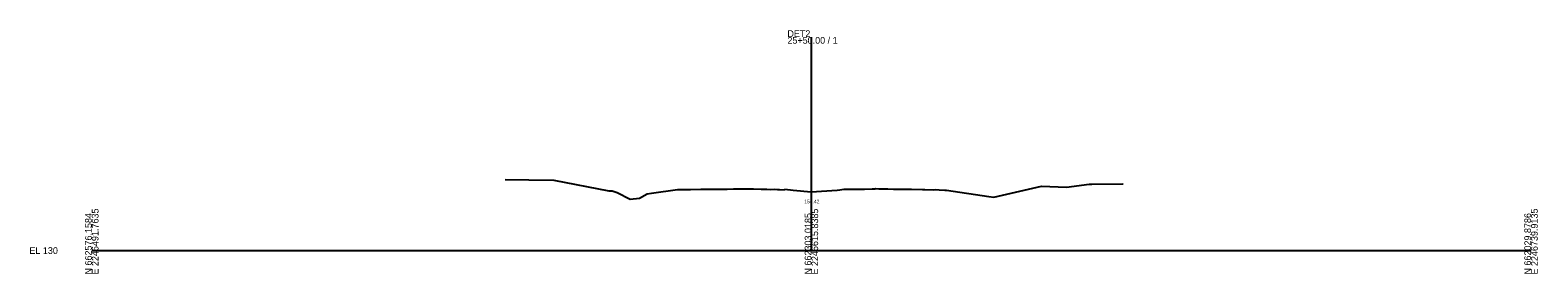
# Model space of a CAD drawing. Extents: x -26 to 603, y -10 to 9526.
# Drawn here: x -26 to 603, y 8490 to 8592 of the extents above; entities that cross this region are included whole.
import ezdxf

# ---------------------------------------------------------------- set-up
doc = ezdxf.new("R2010")
doc.units = 0
for name, color, linetype in [('Default', 7, 'Continuous'), ('Exist Cross Section Cell', 7, 'Continuous'), ('Exist XS Center Line Elevation Label', 7, 'Continuous'), ('Exist XS Ground Line', 7, 'Continuous')]:
    doc.layers.add(name, color=color, linetype=linetype)

msp = doc.modelspace()

# ---------------------------------------------------------------- linework, layer by layer
at = {"layer": 'Exist Cross Section Cell'}
for p, q in [((300, 8500), (300, 8588.93)), ((0, 8500), (300, 8500)), ((300, 8500), (600, 8500))]:
    msp.add_line(p, q, dxfattribs=at)
at = {"layer": 'Exist XS Ground Line'}
for p, q in [((172.27, 8529.64), (182.19, 8529.48)), ((182.19, 8529.48), (192.62, 8529.37)), ((192.62, 8529.37), (215.52, 8524.82)), ((215.52, 8524.82), (216.9, 8524.8)), ((216.9, 8524.8), (219.09, 8524.18)), ((219.09, 8524.18), (224.51, 8521.41)), ((228.36, 8521.82), (231.48, 8523.58)), ((231.48, 8523.58), (233.31, 8523.85)), ((233.31, 8523.85), (244.15, 8525.43)), ((244.15, 8525.43), (246.05, 8525.47)), ((246.05, 8525.47), (246.86, 8525.45)), ((246.86, 8525.45), (247.97, 8525.42)), ((247.97, 8525.42), (248.48, 8525.41)), ((248.48, 8525.41), (249.61, 8525.44)), ((249.61, 8525.44), (253.89, 8525.53)), ((253.89, 8525.53), (257.45, 8525.58)), ((257.45, 8525.58), (259.38, 8525.59)), ((259.38, 8525.59), (260.36, 8525.6)), ((260.36, 8525.6), (260.76, 8525.6)), ((260.76, 8525.6), (261.38, 8525.6)), ((261.38, 8525.6), (261.72, 8525.61)), ((261.72, 8525.61), (263.88, 8525.62)), ((263.88, 8525.62), (264.87, 8525.62)), ((264.87, 8525.62), (267.51, 8525.64)), ((267.51, 8525.64), (270.37, 8525.66)), ((270.37, 8525.66), (271.44, 8525.67)), ((271.44, 8525.67), (273.24, 8525.7)), ((273.24, 8525.7), (273.79, 8525.71)), ((273.79, 8525.71), (275.47, 8525.66)), ((275.47, 8525.66), (275.86, 8525.66)), ((275.86, 8525.66), (278.99, 8525.6)), ((278.99, 8525.6), (281.35, 8525.53)), ((281.35, 8525.53), (282.77, 8525.48)), ((282.77, 8525.48), (284.66, 8525.55)), ((284.66, 8525.55), (285.81, 8525.42)), ((285.81, 8525.42), (286.74, 8525.42)), ((286.74, 8525.42), (288.62, 8525.29)), ((288.62, 8525.29), (288.9, 8525.58)), ((288.9, 8525.58), (292.41, 8525.18)), ((292.41, 8525.18), (299.93, 8524.41)), ((299.93, 8524.41), (310.74, 8525.17)), ((310.74, 8525.17), (311.82, 8525.25)), ((311.82, 8525.25), (313.51, 8525.51)), ((313.51, 8525.51), (313.86, 8525.51)), ((313.86, 8525.51), (314.84, 8525.51)), ((314.84, 8525.51), (315.44, 8525.54)), ((315.44, 8525.54), (315.75, 8525.55)), ((315.75, 8525.55), (316.75, 8525.54)), ((316.75, 8525.54), (319.79, 8525.59)), ((319.79, 8525.59), (322.15, 8525.63)), ((322.15, 8525.63), (325.28, 8525.67)), ((325.28, 8525.67), (326.46, 8525.7)), ((326.46, 8525.7), (326.86, 8525.77)), ((326.86, 8525.77), (328.05, 8525.69)), ((328.05, 8525.69), (329.18, 8525.69)), ((329.18, 8525.69), (330.77, 8525.67)), ((330.77, 8525.67), (331.86, 8525.65)), ((331.86, 8525.65), (334.24, 8525.62)), ((334.24, 8525.62), (335.63, 8525.61)), ((335.63, 8525.61), (336.27, 8525.6)), ((336.27, 8525.6), (338.32, 8525.57)), ((338.32, 8525.57), (338.97, 8525.57)), ((338.97, 8525.57), (339.51, 8525.55)), ((339.51, 8525.55), (340.37, 8525.54)), ((340.37, 8525.54), (341.76, 8525.51)), ((341.76, 8525.51), (346.33, 8525.45)), ((346.33, 8525.45), (347.25, 8525.43)), ((347.25, 8525.43), (350.74, 8525.35)), ((350.74, 8525.35), (351.89, 8525.36)), ((351.89, 8525.36), (353.29, 8525.29)), ((353.29, 8525.29), (355.57, 8525.18)), ((355.57, 8525.18), (356.26, 8525.15)), ((356.26, 8525.15), (373.98, 8522.53)), ((376.06, 8522.21), (395.99, 8526.78)), ((395.99, 8526.78), (406.37, 8526.39)), ((406.37, 8526.39), (415.77, 8527.63)), ((415.77, 8527.63), (416.86, 8527.64)), ((416.86, 8527.64), (429.77, 8527.78)), ((429.77, 8527.78), (429.83, 8527.66)), ((224.51, 8521.41), (228.36, 8521.82)), ((373.98, 8522.53), (376.06, 8522.21))]:
    msp.add_line(p, q, dxfattribs=at)

# ---------------------------------------------------------------- texts
at = {"layer": 'Default'}
msp.add_text('-', height=0.0001, dxfattribs=at).set_placement((0, 8500))
msp.add_text('-', height=0.0001, dxfattribs=at).set_placement((0, 8500))
at = {"layer": 'Exist Cross Section Cell'}
for s, p in [('25+50.00 / 1', (290, 8586.13)), ('DET2', (290, 8588.93)), ('EL 130', (-26, 8498.6))]:
    msp.add_text(s, height=2.8, dxfattribs=at).set_placement(p)
for s, p in [('E 2246491.7635', (2.8, 8490)), ('E 2246615.8385', (302.8, 8490)), ('E 2246739.9135', (602.8, 8490)), ('N 662576.1584', (0, 8490)), ('N 662303.0185', (300, 8490)), ('N 662029.8786', (600, 8490))]:
    msp.add_text(s, height=2.8, rotation=90, dxfattribs=at).set_placement(p)
at = {"layer": 'Exist XS Center Line Elevation Label'}
msp.add_text('154.42', height=1.5, dxfattribs=at).set_placement((297.02, 8519.67))

doc.saveas('drawing.dxf')
